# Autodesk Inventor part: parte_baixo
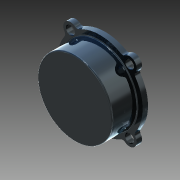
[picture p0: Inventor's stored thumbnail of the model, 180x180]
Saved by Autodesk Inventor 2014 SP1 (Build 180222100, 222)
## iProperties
Created: 2016-04
Part Number: parte_baixo
Material: Genérico
Document SubType Name: Modeling
Designer: Celiberto
Density: 1 g/cm^3
Appearance: Acetinada manchada - Azul
Author: Celiberto
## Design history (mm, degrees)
sketch "Esboço1"
  geometry: C1 r 10.5 at (0, 0); 1 further point
  constraints: 1 centre point, 1 coincident
  dimensions: "d0" = 21 diameter of C1
extrude "Extrusão1" new body sketch "Esboço1" distance "d1" = 8.6; taper "d2" = 0 deg
sketch "Esboço2"
  geometry: C1 r 10.5 at (0, 0) reference; C2 r 12 at (0, 0)
  constraints: 1 centre point, 1 coincident
  dimensions: "d3" = 24 diameter of C2
extrude "Extrusão2" join sketch "Esboço2" distance "d4" = 1.5; taper "d5" = 0 deg
sketch "Esboço3"
  geometry: C1 r 12 at (0, 0) reference; C2 r 9 at (0, 0)
  constraints: 1 centre point, 1 coincident
  dimensions: "d6" = 18 diameter of C2
extrude "Extrusão3" cut sketch "Esboço3" distance "d7" = 7.1; taper "d8" = 0 deg
sketch "Esboço4"
  geometry: L1 (-17.505, 9)-(22.685, 9); L2 (-16.85, -9)-(21.554, -9); L3 (-0.893, 0)-(-18.696, 0); C1 r 12 at (0, 0) reference; C2 r 2 at (-8.31, 9); C3 r 2 at (8.31, 9); C4 r 2 at (8.31, -9); C5 r 2 at (-8.31, -9); A1 r 12.25 centre (0, 0) between (-8.31, 9) and (8.31, 9)
  constraints: 6 end point, 5 centre point, 4 point on circle, 4 point on line, 2 parallel, 1 coincident, 1 horizontal
  dimensions: "d9" = 24.5 diameter of A1; "d10" = 9 distance between parallel lines of L3 L1; "d11" = 9 distance between parallel lines of L2 L3; "d12" = 4 diameter of C2; "d13" = 4 diameter of C3; "d14" = 4 diameter of C4; "d15" = 4 diameter of C5
extrude "Extrusão4" join sketch "Esboço4" distance "d16" = 1.5; taper "d17" = 0 deg
sketch "Esboço5"
  geometry: C1 r 1.25 at (-8.31, 9); C2 r 1.25 at (8.31, 9); C3 r 1.25 at (8.31, -9); C4 r 1.25 at (-8.31, -9); A1 r 2 centre (8.31, -9) between (6.594, -10.026) and (9.47, -7.37) reference; A2 r 2 centre (8.31, 9) between (9.47, 7.37) and (6.594, 10.026) reference; A3 r 2 centre (-8.31, 9) between (-6.594, 10.026) and (-9.47, 7.37) reference; A4 r 2 centre (-8.31, -9) between (-9.47, -7.37) and (-6.594, -10.026) reference
  constraints: 4 centre point, 4 coincident
  dimensions: "d18" = 2.5 diameter of C1; "d19" = 2.5 diameter of C2; "d20" = 2.5 diameter of C3; "d21" = 2.5 diameter of C4
extrude "Extrusão5" cut sketch "Esboço5" distance "d22" = 1.5; taper "d23" = 0 deg
fillet "Arredondamento1" dims "d24" = 1
fillet "Arredondamento2" dims "d25" = 0.4
fillet "Arredondamento3" dims "d26" = 0.4
node "Sólido1"
